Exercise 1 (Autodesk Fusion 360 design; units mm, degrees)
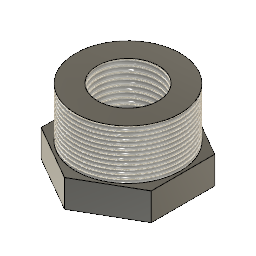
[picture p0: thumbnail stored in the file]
sketch "Sketch1" plane through (0, 0, 0) normal (0, 0, 1) x axis (1, 0, 0)
  line L1 (0, 23) -> (19.9186, 11.5)
  line L2 (-19.9186, 11.5) -> (0, 23)
  line L3 (-19.9186, -11.5) -> (-19.9186, 11.5)
  line L4 (0, -23) -> (-19.9186, -11.5)
  line L5 (19.9186, -11.5) -> (0, -23)
  line L6 (19.9186, 11.5) -> (19.9186, -11.5)
  circle C1 centre (0, 0) radius 11.0115
  point P1 (0, 0)
  point P8 (0, 0)
  point P9 (0, 0)
  point P2 (19.9186, 11.5)
  point P7 (19.9186, -11.5)
  coincident P1 P8
  vertical L6
  coincident P8 P9
  dimension "d1" distance P2 P7 = 23
  dimension "d2" diameter C1 = 22.023
extrude "Extrude1" new body sketch "Sketch1" along normal blind 10
sketch "Sketch2" plane through (0, 0, 10) normal (0, 0, 1) x axis (-1, 0, 0)
  line L1 (-19.9186, -11.5) -> (-19.9186, 11.5)
  line L2 (0, -23) -> (-19.9186, -11.5)
  line L3 (19.9186, -11.5) -> (0, -23)
  line L4 (19.9186, 11.5) -> (19.9186, -11.5)
  line L5 (0, 23) -> (19.9186, 11.5)
  line L6 (-19.9186, 11.5) -> (0, 23)
  circle C1 centre (0, 0) radius 11.0115
  circle C2 centre (0, 0) radius 11.0115
  circle C3 centre (0, 0) radius 18.925
  point P1 (0, 0)
  point P9 (0, 0)
  coincident P1 P9
  concentric C2 C3
  dimension "d5" diameter C3 = 37.85
  dimension "d6" diameter C2 = 22.023
extrude "Extrude2" add sketch "Sketch2" profile of C1 C2 C3 along normal blind 18
thread "Thread7"
thread "Thread8"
